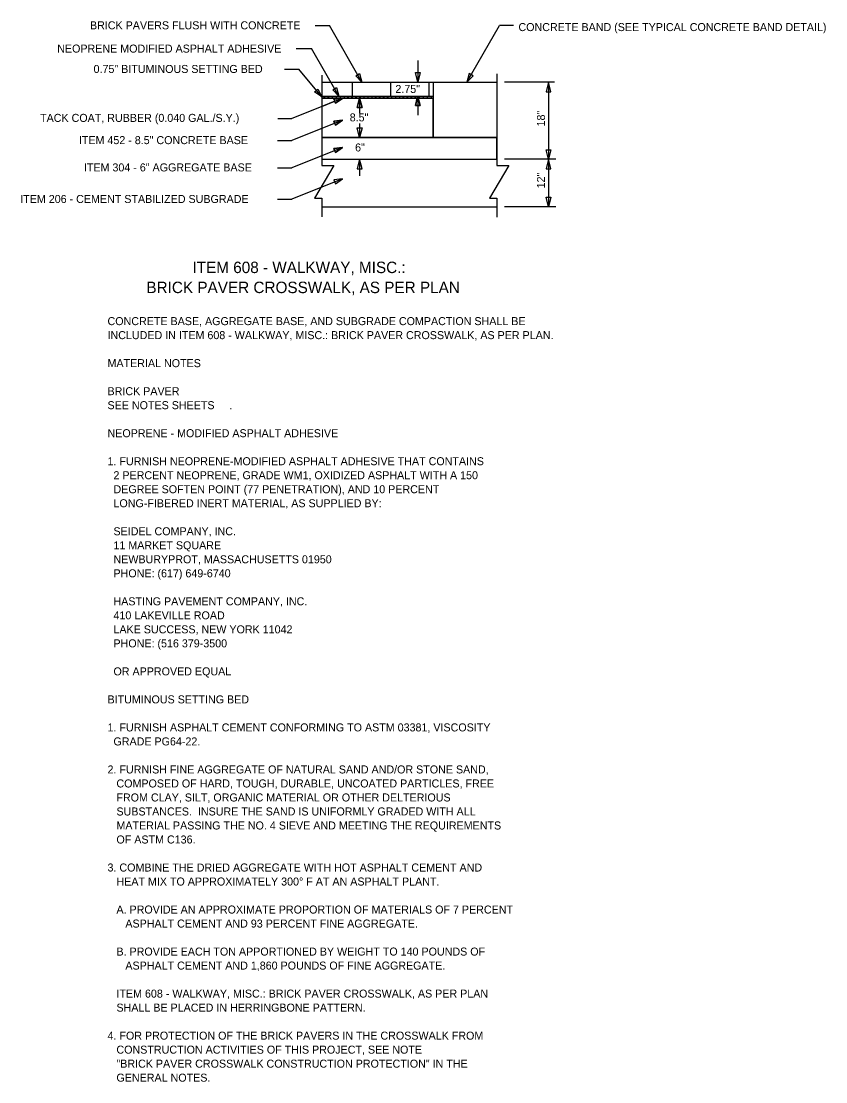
# Model space of a CAD drawing. Extents: x -503 to 1, y -1113 to -115.
# Drawn here: x -502.8 to -362.1, y -1110.8 to -925.3 of the extents above; entities that cross this region are included whole.
import ezdxf

# ---------------------------------------------------------------- set-up
doc = ezdxf.new("R2010")
doc.units = 0
for name, color, linetype in [('SH_Data', 7, 'Continuous'), ('SH_Text', 7, 'Continuous'), ('TX_X_5', 7, 'Continuous')]:
    doc.layers.add(name, color=color, linetype=linetype)

msp = doc.modelspace()

# ---------------------------------------------------------------- linework, layer by layer
at = {"layer": 'SH_Data'}
for p, q in [((-450.24, -935.97), (-419.59, -935.97)), ((-444.93, -935.97), (-444.93, -938.41)), ((-438.22, -935.97), (-438.22, -938.41)), ((-431.51, -935.97), (-431.51, -938.41)), ((-430.76, -935.97), (-430.76, -945.65)), ((-450.24, -938.41), (-430.76, -938.41)), ((-450.24, -938.76), (-430.76, -938.76)), ((-450.24, -938.76), (-450.24, -940.23)), ((-447.96, -939.32), (-450.24, -940.23)), ((-450.24, -940.23), (-447.96, -939.32)), ((-450.24, -940.23), (-450.24, -944.07)), ((-447.82, -939.67), (-447.96, -939.32)), ((-446.57, -938.76), (-447.82, -939.67)), ((-446.39, -938.76), (-446.57, -938.76)), ((-443.63, -938.76), (-444.32, -938.76)), ((-444.02, -940.44), (-443.6, -938.76)), ((-443.6, -938.76), (-443.63, -938.76)), ((-442.93, -938.76), (-443.6, -938.76)), ((-442.24, -938.76), (-442.93, -938.76)), ((-436.71, -938.76), (-437.4, -938.76)), ((-436.02, -938.76), (-436.71, -938.76)), ((-435.33, -938.76), (-436.02, -938.76)), ((-433.25, -938.76), (-433.35, -938.76)), ((-432.56, -938.76), (-433.25, -938.76)), ((-431.87, -938.76), (-432.56, -938.76)), ((-430.76, -945.65), (-430.76, -938.76)), ((-447.98, -943.17), (-448.12, -942.82)), ((-447.84, -943.52), (-447.98, -943.17)), ((-443.6, -945.65), (-444.02, -943.97)), ((-444.02, -943.97), (-443.6, -943.97)), ((-443.6, -943.97), (-443.18, -943.97)), ((-443.18, -943.97), (-443.6, -945.65)), ((-450.24, -944.07), (-450.24, -945.65)), ((-450.24, -945.65), (-419.59, -945.65)), ((-443.6, -945.65), (-450.24, -945.65)), ((-450.24, -945.65), (-450.24, -948.86)), ((-450.24, -945.65), (-443.6, -945.65)), ((-430.76, -945.65), (-443.6, -945.65)), ((-443.6, -945.65), (-430.76, -945.65)), ((-419.59, -945.65), (-430.76, -945.65)), ((-419.59, -949.47), (-419.59, -945.65)), ((-450.24, -948.86), (-450.24, -949.47)), ((-450.24, -949.47), (-419.59, -949.47)), ((-450.24, -957.77), (-419.59, -957.77))]:
    msp.add_line(p, q, dxfattribs=at)
for points in [[(-450.24, -934.75), (-450.24, -950.56), (-448.14, -950.56), (-451.51, -956.27), (-450.24, -956.27), (-450.24, -959.51)], [(-450.24, -934.75), (-450.24, -950.56), (-448.14, -950.56), (-451.51, -956.27), (-450.24, -956.27), (-450.24, -959.51)], [(-419.59, -934.53), (-419.59, -950.56), (-417.49, -950.56), (-420.86, -956.27), (-419.59, -956.27), (-419.59, -959.6)], [(-446.57, -938.76), (-447.09, -938.76), (-447.78, -938.76), (-448.47, -938.76), (-449.16, -938.76), (-449.85, -938.76), (-450.24, -938.76)], [(-447.96, -939.32), (-448.1, -938.97), (-446.57, -938.76)], [(-444.32, -938.76), (-445.01, -938.76), (-445.7, -938.76), (-446.39, -938.76)], [(-443.6, -938.76), (-443.18, -940.44), (-443.6, -940.44), (-444.02, -940.44)], [(-440.86, -938.76), (-441.55, -938.76), (-442.24, -938.76)], [(-438.78, -938.76), (-439.48, -938.76), (-440.17, -938.76), (-440.86, -938.76)], [(-437.4, -938.76), (-438.09, -938.76), (-438.78, -938.76)], [(-433.53, -938.76), (-433.94, -938.76), (-434.63, -938.76), (-435.33, -938.76)], [(-433.35, -938.76), (-433.02, -940.09), (-433.44, -940.09), (-433.86, -940.09), (-433.53, -938.76)], [(-430.76, -938.76), (-431.17, -938.76), (-431.87, -938.76)], [(-448.12, -942.82), (-446.59, -942.61), (-447.84, -943.52)], [(-448.12, -947.61), (-446.59, -947.4), (-447.84, -948.3), (-447.98, -947.96), (-448.12, -947.61)], [(-450.24, -949.47), (-443.6, -949.47), (-419.59, -949.47)]]:
    msp.add_lwpolyline(points, dxfattribs=at)
at = {"layer": 'SH_Text'}
for p, q in [((-433.44, -932.21), (-433.44, -935.97)), ((-409.5, -935.97), (-418.25, -935.97)), ((-410.56, -935.97), (-410.56, -957.77)), ((-433.44, -938.41), (-433.44, -941.77)), ((-443.6, -938.76), (-443.6, -941.44)), ((-443.6, -943.2), (-443.6, -945.65)), ((-443.6, -949.47), (-443.6, -952.34)), ((-409.31, -949.47), (-418.25, -949.47)), ((-409.31, -957.77), (-418.25, -957.77))]:
    msp.add_line(p, q, dxfattribs=at)
for points in [[(-433.02, -934.29), (-433.44, -935.97), (-433.86, -934.29)], [(-410.14, -937.65), (-410.56, -935.97), (-410.98, -937.65)], [(-433.02, -940.09), (-433.44, -938.41), (-433.86, -940.09)], [(-443.18, -940.44), (-443.6, -938.76), (-444.02, -940.44)], [(-443.18, -943.97), (-443.6, -945.65), (-444.02, -943.97)], [(-443.18, -951.15), (-443.6, -949.47), (-444.02, -951.15)], [(-410.14, -947.79), (-410.56, -949.47), (-410.98, -947.79)], [(-410.14, -951.15), (-410.56, -949.47), (-410.98, -951.15)], [(-410.14, -956.09), (-410.56, -957.77), (-410.98, -956.09)]]:
    msp.add_lwpolyline(points, close=True, dxfattribs=at)
at = {"layer": 'TX_X_5'}
for p, q in [((-451.37, -926.05), (-448.9, -926.05)), ((-443.2, -935.97), (-448.9, -926.05)), ((-424.85, -935.97), (-419.15, -926.05)), ((-416.68, -926.05), (-419.15, -926.05)), ((-454.72, -930.1), (-452, -930.1)), ((-447.23, -938.41), (-452, -930.1)), ((-456.77, -933.73), (-454.27, -933.73)), ((-450.24, -938.57), (-454.27, -933.73)), ((-449.85, -938.76), (-449.65, -938.41)), ((-449.16, -938.76), (-448.96, -938.41)), ((-448.47, -938.76), (-448.27, -938.41)), ((-447.78, -938.76), (-447.58, -938.41)), ((-447.09, -938.76), (-446.88, -938.41)), ((-446.39, -938.76), (-446.19, -938.41)), ((-445.7, -938.76), (-445.5, -938.41)), ((-445.01, -938.76), (-444.81, -938.41)), ((-444.32, -938.76), (-444.12, -938.41)), ((-443.63, -938.76), (-443.42, -938.41)), ((-442.93, -938.76), (-442.73, -938.41)), ((-442.24, -938.76), (-442.04, -938.41)), ((-441.55, -938.76), (-441.35, -938.41)), ((-440.86, -938.76), (-440.66, -938.41)), ((-440.17, -938.76), (-439.97, -938.41)), ((-439.48, -938.76), (-439.27, -938.41)), ((-438.78, -938.76), (-438.58, -938.41)), ((-438.09, -938.76), (-437.89, -938.41)), ((-437.4, -938.76), (-437.2, -938.41)), ((-436.71, -938.76), (-436.51, -938.41)), ((-436.02, -938.76), (-435.82, -938.41)), ((-435.33, -938.76), (-435.12, -938.41)), ((-434.63, -938.76), (-434.43, -938.41)), ((-433.94, -938.76), (-433.74, -938.41)), ((-433.25, -938.76), (-433.05, -938.41)), ((-432.56, -938.76), (-432.36, -938.41)), ((-431.87, -938.76), (-431.66, -938.41)), ((-431.17, -938.76), (-430.97, -938.41)), ((-446.57, -938.76), (-455.47, -942.32)), ((-457.94, -942.32), (-455.47, -942.32)), ((-446.59, -942.61), (-455.49, -946.17)), ((-457.96, -946.17), (-455.49, -946.17)), ((-446.59, -947.4), (-455.49, -950.96)), ((-457.96, -950.96), (-455.49, -950.96)), ((-446.59, -952.88), (-455.49, -956.44)), ((-457.96, -956.44), (-455.49, -956.44))]:
    msp.add_line(p, q, dxfattribs=at)
for points in [[(-443.63, -934.48), (-443.2, -935.97), (-444.28, -934.85)], [(-424.42, -934.48), (-424.85, -935.97), (-423.77, -934.85)], [(-450.91, -937.18), (-450.24, -938.57), (-451.49, -937.66)], [(-447.65, -936.92), (-447.23, -938.41), (-448.3, -937.3)], [(-447.82, -939.67), (-446.57, -938.76), (-448.1, -938.97)], [(-447.84, -943.52), (-446.59, -942.61), (-448.12, -942.82)], [(-447.84, -948.3), (-446.59, -947.4), (-448.12, -947.61)], [(-447.84, -953.78), (-446.59, -952.88), (-448.12, -953.09)]]:
    msp.add_lwpolyline(points, close=True, dxfattribs=at)

# ---------------------------------------------------------------- texts
at = {"layer": 'SH_Text'}
for s, rotation, p in [('2.75"', 360, (-437.35, -937.87)), ('8.5"', 360, (-445.34, -942.84)), ('18"', 90, (-411.18, -943.73)), ('6"', 360, (-444.4, -948.1)), ('12"', 90, (-411.18, -954.56))]:
    msp.add_text(s, height=1.4, rotation=rotation, dxfattribs=at).set_placement(p)
for s, height, p in [('ITEM 608 - WALKWAY, MISC.:', 2, (-472.85, -969.37)), ('BRICK PAVER CROSSWALK, AS PER PLAN', 2, (-480.91, -972.87)), ('CONCRETE BASE, AGGREGATE BASE, AND SUBGRADE COMPACTION SHALL BE', 1.4, (-487.71, -978.47)), ('INCLUDED IN ITEM 608 - WALKWAY, MISC.: BRICK PAVER CROSSWALK, AS PER PLAN.', 1.4, (-487.71, -980.92)), ('MATERIAL NOTES', 1.4, (-487.71, -985.82)), ('BRICK PAVER', 1.4, (-487.71, -990.72)), ('SEE NOTES SHEETS     .', 1.4, (-487.71, -993.17)), ('NEOPRENE - MODIFIED ASPHALT ADHESIVE', 1.4, (-487.71, -998.07)), ('1. FURNISH NEOPRENE-MODIFIED ASPHALT ADHESIVE THAT CONTAINS', 1.4, (-487.71, -1002.97)), ('  2 PERCENT NEOPRENE, GRADE WM1, OXIDIZED ASPHALT WITH A 150 ', 1.4, (-487.71, -1005.42)), ('  DEGREE SOFTEN POINT (77 PENETRATION), AND 10 PERCENT ', 1.4, (-487.71, -1007.87)), ('  LONG-FIBERED INERT MATERIAL, AS SUPPLIED BY:', 1.4, (-487.71, -1010.32)), ('  SEIDEL COMPANY, INC.', 1.4, (-487.71, -1015.22)), ('  11 MARKET SQUARE', 1.4, (-487.71, -1017.67)), ('  NEWBURYPROT, MASSACHUSETTS 01950', 1.4, (-487.71, -1020.12)), ('  PHONE: (617) 649-6740', 1.4, (-487.71, -1022.57)), ('  HASTING PAVEMENT COMPANY, INC.', 1.4, (-487.71, -1027.47)), ('  410 LAKEVILLE ROAD', 1.4, (-487.71, -1029.92)), ('  LAKE SUCCESS, NEW YORK 11042', 1.4, (-487.71, -1032.37)), ('  PHONE: (516 379-3500', 1.4, (-487.71, -1034.82)), ('  OR APPROVED EQUAL', 1.4, (-487.71, -1039.72)), ('BITUMINOUS SETTING BED', 1.4, (-487.71, -1044.62)), ('1. FURNISH ASPHALT CEMENT CONFORMING TO ASTM 03381, VISCOSITY', 1.4, (-487.71, -1049.52)), ('  GRADE PG64-22.', 1.4, (-487.71, -1051.97)), ('2. FURNISH FINE AGGREGATE OF NATURAL SAND AND/OR STONE SAND,', 1.4, (-487.71, -1056.87)), ('   COMPOSED OF HARD, TOUGH, DURABLE, UNCOATED PARTICLES, FREE', 1.4, (-487.71, -1059.32)), ('   FROM CLAY, SILT, ORGANIC MATERIAL OR OTHER DELTERIOUS', 1.4, (-487.71, -1061.77)), ('   SUBSTANCES.  INSURE THE SAND IS UNIFORMLY GRADED WITH ALL', 1.4, (-487.71, -1064.22)), ('   MATERIAL PASSING THE NO. 4 SIEVE AND MEETING THE REQUIREMENTS', 1.4, (-487.71, -1066.67)), ('   OF ASTM C136.', 1.4, (-487.71, -1069.12)), ('3. COMBINE THE DRIED AGGREGATE WITH HOT ASPHALT CEMENT AND', 1.4, (-487.71, -1074.02)), ('   HEAT MIX TO APPROXIMATELY 300%%D F AT AN ASPHALT PLANT.', 1.4, (-487.71, -1076.47)), ('   A. PROVIDE AN APPROXIMATE PROPORTION OF MATERIALS OF 7 PERCENT', 1.4, (-487.71, -1081.37)), ('      ASPHALT CEMENT AND 93 PERCENT FINE AGGREGATE.', 1.4, (-487.71, -1083.82)), ('   B. PROVIDE EACH TON APPORTIONED BY WEIGHT TO 140 POUNDS OF', 1.4, (-487.71, -1088.72)), ('      ASPHALT CEMENT AND 1,860 POUNDS OF FINE AGGREGATE.', 1.4, (-487.71, -1091.17)), ('   ITEM 608 - WALKWAY, MISC.: BRICK PAVER CROSSWALK, AS PER PLAN', 1.4, (-487.71, -1096.07)), ('   SHALL BE PLACED IN HERRINGBONE PATTERN.', 1.4, (-487.71, -1098.52)), ('4. FOR PROTECTION OF THE BRICK PAVERS IN THE CROSSWALK FROM', 1.4, (-487.71, -1103.42)), ('   CONSTRUCTION ACTIVITIES OF THIS PROJECT, SEE NOTE', 1.4, (-487.71, -1105.87)), ('   "BRICK PAVER CROSSWALK CONSTRUCTION PROTECTION" IN THE ', 1.4, (-487.71, -1108.32)), ('   GENERAL NOTES.', 1.4, (-487.71, -1110.77))]:
    msp.add_text(s, height=height, dxfattribs=at).set_placement(p)
at = {"layer": 'TX_X_5'}
for s, p in [('BRICK PAVERS FLUSH WITH CONCRETE', (-490.78, -926.74)), ('CONCRETE BAND (SEE TYPICAL CONCRETE BAND DETAIL)', (-415.82, -927.05)), ('NEOPRENE MODIFIED ASPHALT ADHESIVE', (-496.51, -930.81)), ('0.75" BITUMINOUS SETTING BED', (-490.15, -934.37)), ('TACK COAT, RUBBER (0.040 GAL./S.Y.)', (-499.51, -942.93)), ('ITEM 452 - 8.5" CONCRETE BASE', (-492.72, -946.82)), ('ITEM 304 - 6" AGGREGATE BASE', (-491.84, -951.59)), ('ITEM 206 - CEMENT STABILIZED SUBGRADE', (-502.98, -957.11))]:
    msp.add_text(s, height=1.4, dxfattribs=at).set_placement(p)

doc.saveas('drawing.dxf')
